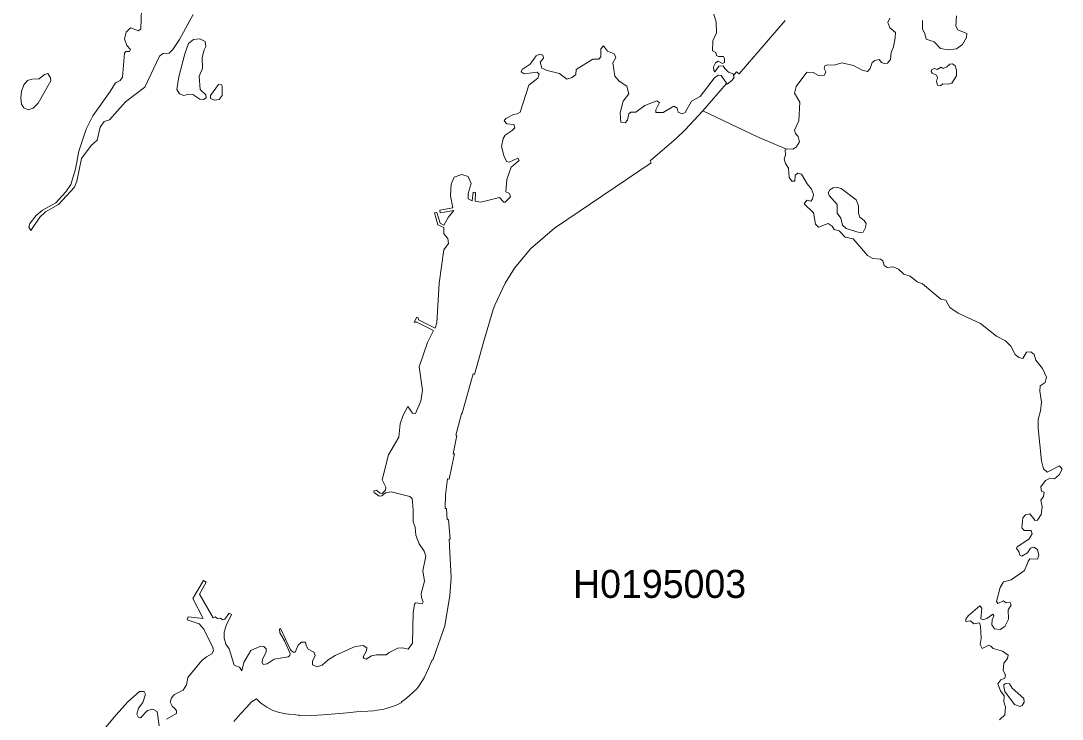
# Model space of a CAD drawing. Extents: x 369010 to 739155, y 6377141 to 6616555.
# Drawn here: x 470758 to 474471, y 6492532 to 6495023 of the extents above; entities that cross this region are included whole.
import ezdxf
from ezdxf.enums import TextEntityAlignment as Align

# ---------------------------------------------------------------- set-up
doc = ezdxf.new("R2010")
doc.units = 0
doc.header["$LTSCALE"] = 40
doc.layers.add('1', color=7, linetype='Continuous', lineweight=13)
doc.layers.add('2', color=7, linetype='Continuous')

msp = doc.modelspace()

# ---------------------------------------------------------------- linework, layer by layer
at = {"layer": '1'}
for points in [[(471189.06, 6495100.49), (471185.92, 6494995.06), (471177.81, 6494987.61), (471148.68, 6494997.87), (471133.12, 6494983.31), (471127.17, 6494958.48), (471135.77, 6494934.82), (471149.18, 6494920.91), (471145.54, 6494913.8), (471132.63, 6494913.8), (471127.17, 6494908.01), (471120.71, 6494821.94), (471112.1, 6494810.03), (471095.55, 6494802.58), (471076.85, 6494770.8), (471013.96, 6494684.74), (470990.29, 6494636.74), (470964.97, 6494558.79), (470953.06, 6494493.75), (470935.84, 6494439.96), (470918.13, 6494412.98), (470882.05, 6494373.76), (470834.72, 6494347.44), (470812.21, 6494328.58), (470789.54, 6494300.61), (470786.89, 6494287.7), (470793.84, 6494275.78), (470825.62, 6494323.11), (470845.48, 6494341.49), (470892.32, 6494367.8), (470948.75, 6494430.2), (470957.36, 6494450.72), (470974.07, 6494532.48), (471008.5, 6494578.65), (471029.52, 6494597.52), (471040.28, 6494644.36), (471054.84, 6494663.72), (471074.2, 6494669.68), (471131.3, 6494733.73), (471199.66, 6494786.36), (471252.29, 6494897.25), (471264.7, 6494906.85), (471286.22, 6494908.01), (471300.28, 6494921.41), (471323.29, 6494956.99), (471371.78, 6495045.7)], [(473483.94, 6495024.69), (473318.77, 6494834.36), (473310.33, 6494841.47), (473299.07, 6494828.73), (473301.23, 6494821.61), (473293.28, 6494810.85), (473276.57, 6494797.12), (473274.25, 6494800.43), (473273.92, 6494800.1), (473189.84, 6494702.28), (473384.47, 6494609.93), (473488.41, 6494565.25), (473491.22, 6494566.9), (473510.26, 6494565.74), (473522.51, 6494572.69), (473534.09, 6494591.23), (473529.95, 6494610.26), (473520.19, 6494621.85), (473516.71, 6494632.77), (473531.77, 6494666.87), (473535.25, 6494733.4), (473517.21, 6494765.18), (473522.51, 6494788.35), (473560.57, 6494839.82), (473583.08, 6494838.66), (473602.77, 6494828.23), (473623.63, 6494829.39), (473628.26, 6494840.98), (473622.47, 6494853.06), (473625.28, 6494862.33), (473634.55, 6494866.3), (473658.38, 6494865.14), (473686.02, 6494873.25), (473726.57, 6494863.82), (473758.35, 6494846.93), (473777.38, 6494842.96), (473786.65, 6494853.39), (473793.6, 6494874.74), (473803.37, 6494881.69), (473818.43, 6494885.17), (473827.2, 6494874.24), (473836.96, 6494870.77), (473848.55, 6494872.42), (473858.97, 6494885.66), (473861.29, 6494910.65), (473869.9, 6494930.84), (473875.69, 6494961.96), (473876.35, 6494981.16), (473856.66, 6494997.87), (473849.71, 6495017.57), (473857.15, 6495032.63)], [(473229.4, 6495047.36), (473237.84, 6495018.23), (473238.33, 6494979.83), (473225.59, 6494951.37), (473223.94, 6494916.12), (473235.69, 6494910.49), (473239, 6494899.9), (473245.62, 6494896.09), (473262.99, 6494896.09), (473267.46, 6494889.3), (473267.46, 6494874.24), (473260.18, 6494870.44), (473243.96, 6494878.71), (473235.02, 6494873.25), (473227.74, 6494859.18), (473229.4, 6494845.78), (473232.87, 6494841.31), (473247.27, 6494862), (473261.84, 6494863.15), (473267.96, 6494852.56), (473281.86, 6494840.31), (473297.59, 6494833.86), (473299.07, 6494828.73), (473310.33, 6494841.47), (473318.77, 6494834.36), (473483.94, 6495024.69)], [(473972.84, 6495024.52), (473972.84, 6494993.24), (473980.95, 6494978.18), (473986.74, 6494957.99), (474014.38, 6494948.22), (474036.89, 6494925.05), (474064.2, 6494919.26), (474094.82, 6494922.74), (474115.51, 6494938.95), (474129.41, 6494963.12), (474131.23, 6494978.18), (474099.45, 6494990.92), (474092.5, 6495004.16), (474094.16, 6495041.24)], [(472819.28, 6494886.16), (472796.94, 6494886.99), (472738.35, 6494850.08), (472736.86, 6494831.21), (472723.78, 6494820.45), (472705.08, 6494815.32), (472678.93, 6494834.85), (472634.91, 6494845.61), (472615.38, 6494854.38), (472609.59, 6494876.06), (472621.17, 6494889.8), (472619.68, 6494900.72), (472607.43, 6494904.2), (472595.19, 6494898.41), (472574.17, 6494868.78), (472545.87, 6494849.25), (472541.56, 6494841.31), (472552.49, 6494834.19), (472598.66, 6494840.65), (472605.94, 6494833.36), (472600.98, 6494818.14), (472569.04, 6494793.64), (472537.92, 6494697.48), (472527.16, 6494690.86), (472514.92, 6494689.54), (472487.44, 6494674.98), (472480.82, 6494667.03), (472490.26, 6494655.45), (472515.58, 6494653.29), (472519.22, 6494641.71), (472510.45, 6494631.61), (472485.13, 6494615.73), (472477.84, 6494603.97), (472472.05, 6494575.01), (472480.66, 6494543.23), (472490.09, 6494521.55), (472499.52, 6494518.57), (472529.81, 6494533.8), (472534.94, 6494525.19), (472506.64, 6494501.36), (472490.75, 6494457.83), (472487.28, 6494412.98), (472500.19, 6494407.36), (472504.49, 6494395.77), (472484.96, 6494376.24), (472480.66, 6494376.24), (472464.77, 6494392.79), (472398.24, 6494376.24), (472378.04, 6494380.54), (472378.71, 6494410.83), (472370.76, 6494411.66), (472367.12, 6494381.21), (472353.38, 6494387.83), (472353.38, 6494407.36), (472363.48, 6494443.44), (472353.38, 6494468.1), (472330.21, 6494474.55), (472303.57, 6494465.12), (472292.64, 6494440.62), (472290.49, 6494399.25), (472297.78, 6494355.88), (472251.43, 6494347.94), (472253.59, 6494337.84), (472301.42, 6494346.62), (472281.06, 6494321.96), (472266.66, 6494294.48), (472253.59, 6494301.76), (472241.34, 6494340), (472233.39, 6494337.84), (472244.32, 6494295.97), (472266.66, 6494286.54), (472266, 6494264.03), (472280.4, 6494246.82), (472283.21, 6494229.44), (472266.66, 6494206.27), (472249.94, 6494087.6), (472241.34, 6493945.77), (472234.88, 6493926.9), (472175.47, 6493956.69), (472174.14, 6493963.81), (472169.68, 6493966.78), (472160.41, 6493947.92), (472169.68, 6493947.92), (472229.75, 6493918.29), (472207.41, 6493876.42), (472178.45, 6493789.53), (472190.2, 6493706.12), (472184.74, 6493666.56), (472164.71, 6493623.03), (472154.61, 6493623.36), (472138.06, 6493648.02), (472120.69, 6493616.58), (472110.43, 6493585.63), (472105.46, 6493537.96), (472069.05, 6493475.73), (472046.21, 6493386.03), (472059.12, 6493359.38), (472057.63, 6493349.45), (472046.54, 6493336.88), (472038.6, 6493339.03)], [(472230.75, 6492752.98), (472269.47, 6492864.86), (472287.85, 6492973.43), (472292.64, 6493037.81), (472287.02, 6493128.18), (472284.7, 6493174.19), (472288.18, 6493174.52), (472282.88, 6493244.03), (472278.25, 6493243.53), (472275.6, 6493284.25), (472270.63, 6493284.08), (472271.63, 6493333.07), (472279.07, 6493389.67), (472285.53, 6493388.51), (472292.98, 6493428.4), (472304.4, 6493478.22), (472299.76, 6493478.88), (472312.17, 6493544.25), (472309.36, 6493544.91), (472313.66, 6493563.12), (472329.22, 6493621.21), (472331.54, 6493623.86), (472370.76, 6493763.55), (472375.56, 6493762.22), (472409.33, 6493880.72), (472442.1, 6493993.43), (472448.22, 6494009.15), (472484.63, 6494087.44), (472518.06, 6494141.39), (472574.99, 6494210.07), (472660.39, 6494283.56), (473005.8, 6494516.75), (473001.5, 6494523.54), (473096, 6494604.31), (473127.28, 6494634.59), (473189.84, 6494702.28), (473273.92, 6494800.1), (473274.25, 6494800.43), (473255.55, 6494828.07), (473243.96, 6494828.89), (473231.05, 6494819.46), (473180.41, 6494753.59), (473149.79, 6494736.54), (473126.62, 6494695.99), (473115.7, 6494691.69), (473101.96, 6494697.48), (473097.66, 6494711.88), (473086.9, 6494719.17), (473047.84, 6494696.66), (473021.69, 6494696.66), (473022.52, 6494705.43), (473034.76, 6494731.41), (473025.33, 6494737.87), (472983.46, 6494721.32), (472950.85, 6494697.48), (472933.48, 6494697.48), (472925.53, 6494690.86), (472921.23, 6494668.52), (472913.28, 6494659.09), (472897.4, 6494662.07), (472895.24, 6494695.33), (472906, 6494737.21), (472925.53, 6494762.53), (472919.08, 6494790.66), (472891.6, 6494808.04), (472876.38, 6494825.42), (472868.43, 6494873.08), (472879.36, 6494892.61), (472873.56, 6494905.03), (472849.57, 6494914.46), (472835.17, 6494933.99), (472826.56, 6494923.73), (472826.56, 6494894.93), (472819.28, 6494886.16)], [(473189.84, 6494702.28), (473127.28, 6494634.59), (473096, 6494604.31), (473001.5, 6494523.54), (473005.8, 6494516.75), (472660.39, 6494283.56), (472574.99, 6494210.07), (472518.06, 6494141.39), (472484.63, 6494087.44), (472448.22, 6494009.15), (472442.1, 6493993.43), (472409.33, 6493880.72), (472375.56, 6493762.22), (472370.76, 6493763.55), (472331.54, 6493623.86), (472329.22, 6493621.21), (472313.66, 6493563.12), (472309.36, 6493544.91), (472312.17, 6493544.25), (472299.76, 6493478.88), (472304.4, 6493478.22), (472292.98, 6493428.4), (472285.53, 6493388.51), (472279.07, 6493389.67), (472271.63, 6493333.07), (472270.63, 6493284.08), (472275.6, 6493284.25), (472278.25, 6493243.53), (472282.88, 6493244.03), (472288.18, 6493174.52), (472284.7, 6493174.19), (472287.02, 6493128.18), (472292.64, 6493037.81), (472287.85, 6492973.43), (472269.47, 6492864.86), (472230.75, 6492752.98), (472226.77, 6492742.88), (472224.95, 6492743.71), (472211.71, 6492713.26), (472196.32, 6492679.83), (472176.63, 6492650.37), (472170.17, 6492641.1), (472142.37, 6492615.44), (472126.81, 6492602.53), (472114.89, 6492594.42), (472116.05, 6492591.61), (472094.37, 6492580.69), (472061.1, 6492570.1), (472047.86, 6492566.95), (472028.5, 6492564.63), (472015.76, 6492562.48), (471954.02, 6492559.01), (471921.25, 6492555.03), (471835.36, 6492547.42), (471795.31, 6492545.1), (471750.45, 6492544.77), (471750.45, 6492546.26), (471701.46, 6492551.56), (471675.65, 6492556.86), (471653.8, 6492564.63), (471635.26, 6492574.73), (471620.7, 6492584.33), (471611.1, 6492592.27), (471598.36, 6492605.51), (471580.81, 6492594.26), (471562.77, 6492574.56), (471541.75, 6492552.55), (471525.86, 6492533.52), (471517.26, 6492523.75)], [(474288.13, 6493862.19), (474269.59, 6493882.38), (474237.15, 6493898.1), (474180.05, 6493943.12), (474100.11, 6493981.02), (474070.65, 6494000.71), (474056.75, 6494027.19), (474038.88, 6494030.67), (473973.01, 6494085.62), (473953.81, 6494092.57), (473928.98, 6494112.76), (473906.47, 6494119.21), (473887.94, 6494137.09), (473868.9, 6494145.2), (473846.89, 6494143.38), (473836.47, 6494150.99), (473831.83, 6494166.55), (473823.23, 6494173.5), (473796.58, 6494175.32), (473777.05, 6494186.74), (473726.08, 6494245.82), (473697.28, 6494252.11), (473676.42, 6494274.62), (473657.89, 6494278.76), (473650.94, 6494290.34), (473637.2, 6494300.77), (473602.44, 6494287.37), (473591.19, 6494297.46), (473584.9, 6494338.01), (473551.3, 6494370.28), (473560.57, 6494383.69), (473575.14, 6494379.55), (473581.42, 6494387.66), (473584.24, 6494403.88), (473577.45, 6494422.42), (473561.73, 6494441.95), (473541.04, 6494476.7), (473528.79, 6494480.18), (473519.53, 6494473.23), (473518.37, 6494450.72), (473506.95, 6494451.21), (473497.68, 6494464.62), (473494.7, 6494498.05), (473484.94, 6494513.77), (473480.3, 6494530.49), (473484.27, 6494543.73), (473483.78, 6494562.76), (473488.41, 6494565.25), (473384.47, 6494609.93), (473189.84, 6494702.28)], [(474266.94, 6492678.17), (474268.93, 6492690.75), (474261.31, 6492705.48), (474262.64, 6492731.96), (474276.54, 6492749.34), (474278.69, 6492760.43), (474257.84, 6492774.49), (474225.07, 6492784.26), (474216.63, 6492793.36), (474209.68, 6492796.01), (474186.01, 6492784.92), (474178.23, 6492798.82), (474181.71, 6492819.84), (474180.38, 6492863.7), (474176.91, 6492875.62), (474156.72, 6492872.8), (474144.14, 6492882.57), (474127.42, 6492880.42), (474128.08, 6492888.86), (474136.52, 6492901.43), (474177.9, 6492937.02), (474184.19, 6492928.74), (474181.38, 6492890.35), (474188.33, 6492886.87), (474202.89, 6492891.01), (474223.91, 6492906.4), (474228.05, 6492900.77), (474221.76, 6492886.21), (474219.77, 6492868.67), (474229.54, 6492854.76), (474250.39, 6492851.95), (474266.45, 6492863.2), (474279.69, 6492889.02), (474278.2, 6492922.45), (474288.79, 6492938.51), (474285.98, 6492948.27), (474271.25, 6492947.61), (474261.48, 6492954.56), (474241.95, 6492944.8), (474237.15, 6492952.41), (474250.39, 6493002.56), (474261.48, 6493022.09), (474288.79, 6493029.2), (474336.78, 6493062.64), (474349.36, 6493094.74), (474356.31, 6493103.85), (474382.96, 6493103.02), (474387.76, 6493117.09), (474383.62, 6493137.28), (474369.55, 6493146.38), (474357.8, 6493142.08), (474348.04, 6493125.36), (474327.02, 6493114.27), (474320.07, 6493117.91), (474316.59, 6493129.83), (474308.32, 6493141.58), (474311.13, 6493147.21), (474352.18, 6493174.35), (474364.75, 6493193.88), (474360.62, 6493205.13), (474336.12, 6493205.13), (474327.85, 6493214.9), (474331.32, 6493250.48), (474340.26, 6493261.57), (474355.65, 6493265.05), (474374.52, 6493241.38), (474383.62, 6493242.7), (474396.2, 6493262.23), (474399.68, 6493289.54), (474394.71, 6493313.87), (474404.48, 6493326.45), (474407.29, 6493341.84), (474397.52, 6493345.98), (474395.37, 6493361.37), (474411.43, 6493383.71), (474428.31, 6493391.66), (474443.37, 6493390.17), (474460.58, 6493404.07), (474471.17, 6493423.6), (474461.24, 6493436.01), (474417.22, 6493413.5), (474404.81, 6493425.59), (474397.86, 6493453.39), (474385.11, 6493570.73), (474385.77, 6493601.35), (474394.38, 6493632.47), (474397.86, 6493663.42), (474391.57, 6493702.64), (474393.22, 6493721.18), (474410.1, 6493733.26), (474414.74, 6493752.46), (474401.33, 6493783.07), (474377.66, 6493812.53), (474371.87, 6493832.73), (474359.13, 6493842.49), (474344.23, 6493840.84), (474330.33, 6493818.82), (474316.43, 6493821.8), (474303.68, 6493832.73), (474288.13, 6493862.19)], [(472038.6, 6493339.03), (472024.86, 6493349.12), (472017.08, 6493346.48), (472017.74, 6493340.85), (472035.62, 6493327.94), (472045.05, 6493328.44), (472058.46, 6493339.85), (472077.99, 6493343.5), (472144.85, 6493326.45), (472152.79, 6493319.83), (472156.93, 6493278.45), (472156.77, 6493236.75), (472164.05, 6493217.22), (472166.2, 6493189.25), (472178.45, 6493157.47), (472195.49, 6493131.32), (472201.95, 6493113.94), (472190.86, 6493061.48), (472197.31, 6493024.57), (472185.89, 6492980.88), (472186.23, 6492966.15), (472192.18, 6492951.42), (472188.87, 6492943.31), (472164.88, 6492947.44), (472162.06, 6492942.98), (472156.77, 6492912.03), (472153.95, 6492803.46), (472139.39, 6492782.44), (472119.03, 6492786.74), (472101.98, 6492785.42), (472071.53, 6492770.52), (472061.1, 6492761.42), (472026.35, 6492761.42), (472008.31, 6492757.78), (471988.95, 6492746.85), (471981.99, 6492748.84), (471978.68, 6492755.13), (471990.93, 6492776.48), (471991.59, 6492787.07), (471978.02, 6492795.02), (471950.22, 6492791.21), (471879.22, 6492759.93), (471854.06, 6492743.88), (471831.88, 6492724.51), (471814.01, 6492718.55), (471798.12, 6492726.66), (471798.12, 6492738.74), (471807.39, 6492759.93), (471802.26, 6492771.02), (471782.89, 6492782.27), (471775.28, 6492795.02), (471773.46, 6492807.1), (471758.73, 6492806.93), (471747.14, 6492796.84), (471735.56, 6492771.68), (471728.44, 6492771.35), (471718.84, 6492779.46), (471683.59, 6492855.42), (471680.11, 6492852.94), (471681.44, 6492840.2), (471697.82, 6492812.23), (471718.51, 6492766.22), (471717.52, 6492759.76), (471710.9, 6492754.96), (471660.92, 6492746.52), (471636.75, 6492729.48), (471621.36, 6492727.82), (471617.89, 6492735.43), (471619.71, 6492746.19), (471632.45, 6492771.68), (471633.11, 6492783.1), (471624.51, 6492791.21), (471612.09, 6492792.7), (471578.5, 6492777.47), (471553.5, 6492733.94), (471545.39, 6492705.31), (471538.11, 6492717.89), (471518.91, 6492724.84), (471500.38, 6492783.76), (471488.63, 6492800.15), (471482.5, 6492821.5), (471483.16, 6492842.18), (471490.12, 6492866.51), (471509.48, 6492905.74), (471500.87, 6492910.54), (471484.65, 6492888.53), (471478.03, 6492887.2), (471469.43, 6492892.33), (471458.5, 6492891.5), (471451.06, 6492897.46), (471444.11, 6492894.32), (471394.95, 6492978.23), (471419.11, 6493020.76), (471408.69, 6493027.55), (471370.79, 6492963.33), (471408.03, 6492892), (471354.9, 6492897.46), (471351.09, 6492886.37), (471393.63, 6492872.8), (471410.18, 6492852.94)], [(471410.18, 6492852.94), (471442.95, 6492787.57), (471444.77, 6492775.65), (471438.81, 6492765.39), (471419.61, 6492754.8), (471403.56, 6492741.06), (471352.75, 6492680.82), (471348.61, 6492655), (471336.69, 6492636.13), (471306.24, 6492620.74), (471294.49, 6492608.16), (471290.85, 6492593.43), (471297.14, 6492578.21), (471307.4, 6492570.92), (471312.36, 6492562.32), (471312.36, 6492553.05), (471277.11, 6492532.03)], [(471517.26, 6492523.75), (471525.86, 6492533.52), (471541.75, 6492552.55), (471562.77, 6492574.56), (471580.81, 6492594.26), (471598.36, 6492605.51), (471611.1, 6492592.27), (471620.7, 6492584.33), (471635.26, 6492574.73), (471653.8, 6492564.63), (471675.65, 6492556.86), (471701.46, 6492551.56), (471750.45, 6492546.26), (471750.45, 6492544.77), (471795.31, 6492545.1), (471835.36, 6492547.42), (471921.25, 6492555.03), (471954.02, 6492559.01), (472015.76, 6492562.48), (472028.5, 6492564.63), (472047.86, 6492566.95), (472061.1, 6492570.1), (472094.37, 6492580.69), (472116.05, 6492591.61), (472114.89, 6492594.42), (472126.81, 6492602.53), (472142.37, 6492615.44), (472170.17, 6492641.1), (472176.63, 6492650.37), (472196.32, 6492679.83), (472211.71, 6492713.26), (472224.95, 6492743.71), (472226.77, 6492742.88), (472230.75, 6492752.98)], [(474248.07, 6492530.37), (474266.11, 6492547.75), (474268.93, 6492575.06), (474262.64, 6492594.59), (474264.13, 6492615.44), (474251.55, 6492633.65), (474241.79, 6492658.64), (474252.21, 6492672.71), (474266.94, 6492678.17)], [(471251.46, 6492508.03), (471244.01, 6492559.67), (471228.95, 6492567.61), (471209.59, 6492563.14), (471184.93, 6492537.66), (471177.48, 6492538.65), (471170.86, 6492550.07), (471177.81, 6492571.59), (471193.04, 6492592.27), (471202.64, 6492622.06), (471197.34, 6492630.67), (471180.79, 6492630.67), (471138.92, 6492594.09), (471097.21, 6492548.41), (471025.38, 6492461.19)]]:
    msp.add_lwpolyline(points, dxfattribs=at)
for points in [[(471411.83, 6494919.59), (471416.96, 6494932.17), (471414.81, 6494948.88), (471395.94, 6494958.65), (471373.44, 6494956.5), (471356.22, 6494942.43), (471342.65, 6494905.85), (471320.64, 6494823.1), (471313.69, 6494777.75), (471323.29, 6494762.69), (471339.51, 6494756.9), (471357.22, 6494761.2), (471370.62, 6494760.71), (471396.44, 6494743.49), (471409.35, 6494742.34), (471418.62, 6494748.79), (471417.46, 6494759.55), (471397.1, 6494778.42), (471394.29, 6494826.25), (471405.71, 6494852.56), (471404.55, 6494892.94)], [(474080.42, 6494869.28), (474070.16, 6494868.28), (474060.06, 6494859.51), (474046.99, 6494853.55), (474039.21, 6494857.86), (474025.64, 6494850.08), (474016.2, 6494852.89), (474006.44, 6494849.09), (474004.45, 6494842.47), (474008.09, 6494836.34), (474022.66, 6494829.56), (474026.63, 6494820.45), (474022.99, 6494806.72), (474027.13, 6494793.48), (474036.89, 6494791.49), (474045.99, 6494798.61), (474067.51, 6494796.79), (474078.27, 6494800.92), (474094.49, 6494827.24), (474094.49, 6494847.1), (474090.18, 6494862.33)], [(470865.17, 6494809.53), (470863.52, 6494819.46), (470854.58, 6494835.51), (470841.67, 6494831.54), (470822.8, 6494816.65), (470796.82, 6494815.16), (470781.26, 6494810.19), (470768.02, 6494794.97), (470760.41, 6494770.8), (470757.76, 6494748.13), (470759.75, 6494725.45), (470768.19, 6494713.04), (470784.08, 6494705.59), (470802.12, 6494712.21), (470819.33, 6494729.59)], [(471475.55, 6494787.19), (471475.06, 6494794.47), (471463.14, 6494796.12), (471433.68, 6494757.4), (471434.18, 6494745.65), (471448.08, 6494740.68), (471464.79, 6494742.83), (471476.05, 6494756.9)], [(473751.23, 6494267.17), (473761.99, 6494269.82), (473770.1, 6494285.71), (473772.09, 6494299.94), (473764.64, 6494311.03), (473749.58, 6494322.78), (473744.94, 6494336.69), (473744.94, 6494362.84), (473736.17, 6494385.18), (473683.54, 6494425.56), (473669.8, 6494429.04), (473654.58, 6494428.04), (473642.16, 6494420.6), (473637.03, 6494410.17), (473640.84, 6494400.4), (473668.31, 6494367.63), (473669.31, 6494337.68), (473682.38, 6494319.14), (473687.84, 6494294.15), (473700.92, 6494282.07)], [(474321.39, 6492578.04), (474328.68, 6492581.35), (474335.46, 6492592.94), (474334.47, 6492606.34), (474293.42, 6492643.08), (474283.66, 6492657.98), (474269.09, 6492660.13), (474263.63, 6492655), (474262.97, 6492648.88), (474266.61, 6492631.33), (474300.7, 6492584.49)]]:
    msp.add_lwpolyline(points, close=True, dxfattribs=at)

# ---------------------------------------------------------------- texts
at = {"layer": '2'}
msp.add_text('H0195003', height=100, dxfattribs=at).set_placement((473035.65, 6492964.8), align=Align.CENTER)

doc.saveas('drawing.dxf')
